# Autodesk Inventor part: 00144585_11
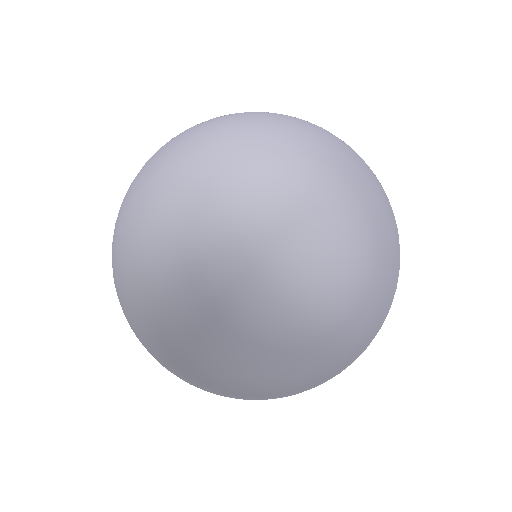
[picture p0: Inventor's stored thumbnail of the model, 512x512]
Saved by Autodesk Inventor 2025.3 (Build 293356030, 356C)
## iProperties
Created: 2021-02
Part Number: 00144585_11
Material: Generico
Document SubType Name: Modeling
Designer: R5800u
Density: 1 g/cm^3
Appearance: Default
Author: TraceParts
Sending System: SolidWorks 2021
Last Author: Albert
Last Saved: 2021-07-28
IsFastener: 1
TYPE: CATASM
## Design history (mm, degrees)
feature "Imported1"
node "Solido1"
